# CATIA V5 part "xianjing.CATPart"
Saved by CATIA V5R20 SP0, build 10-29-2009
Part number: xianjing
Bounding box of the stored display mesh (mm): x -4 to 28, y -4 to 4, z -10 to 10
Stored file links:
  F:\xianjing.CATPart
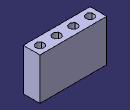
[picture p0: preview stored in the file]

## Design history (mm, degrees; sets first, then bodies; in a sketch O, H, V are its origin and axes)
Body1 (main body)
  Sketch1 on xy-plane, origin (0, 0, 0), H (1, 0, 0), V (0, 1, 0)
    line L1 (4, 4) -> (4, -4)
    line L2 (4, -4) -> (-4, -4)
    line L3 (-4, -4) -> (-4, 4)
    line L4 (-4, 4) -> (4, 4)
    length L4 = 8
    length L1 = 8
    vertical: L1 V, L3 V
    horizontal: L2 H, L4 H
    equidistance: L1 L3 O, L2 L4 O
  Pad1: profile Sketch1, direction (0, 0, 1), length 10, mirrored extent
  Sketch2 on start face of Pad1, origin (1.7458, -0.1113, -10), H (1, 0, 0), V (0, -1, 0)
    point P1 (-1.7458, -0.1113)
    reference projected line E1 (2.2542, 3.8887) -> (2.2542, -4.1113) from edge [start face of Pad1 | face of Pad1 from Sketch1.L1]
    reference projected line E2 (2.2542, -4.1113) -> (-5.7458, -4.1113) from edge [start face of Pad1 | face of Pad1 from Sketch1.L4]
    distance P1 E1 = 4
    distance P1 E2 = 4
  Hole1: placed by Sketch2, at (0, 0, -10) direction (0, 0, 1), diameter 4, through (limit type 3)
  RectPattern1: of the body so far, direction 1 instances 4, spacing 8, along {line type PtPt, FirstPoint vertex [face of Pad1 from Sketch1.L2 | start face of Pad1 | face of Pad1 from Sketch1.L3], SecondPoint vertex [face of Pad1 from Sketch1.L2 | start face of Pad1 | face of Pad1 from Sketch1.L1]}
